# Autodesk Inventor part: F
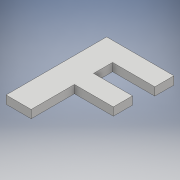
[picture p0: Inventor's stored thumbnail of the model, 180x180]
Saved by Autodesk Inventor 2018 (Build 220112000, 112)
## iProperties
Created: 2020-11
Part Number: F
Material: Genérico
Document SubType Name: Modeling
Designer: ULISES
Density: 1 g/cm^3
Appearance: Valor por defecto
Author: ULISES
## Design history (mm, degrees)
sketch "Boceto1"
  geometry: L1 (5.521, 40.076)-(7.707, 40.076); L2 (7.707, 40.076)-(7.707, 37.028); L3 (7.707, 37.028)-(5.521, 37.028); L4 (5.521, 37.028)-(5.521, 40.076); L5 (0, 0)-(40, 0); L6 (40, 0)-(40, 40); L7 (40, 40)-(0, 40); L8 (0, 40)-(0, 0)
  constraints: 8 end point, 2 parallel, 1 horizontal, 1 perpendicular, 2 other
  dimensions: "d0" = 40 distance of L7.end L5.start; "d1" = 40 distance of L6.end L7.end
extrude "Extrusión1" new body sketch "Boceto1" distance "d2" = 3.2; taper "d3" = 0 deg
node "Sólido1"
